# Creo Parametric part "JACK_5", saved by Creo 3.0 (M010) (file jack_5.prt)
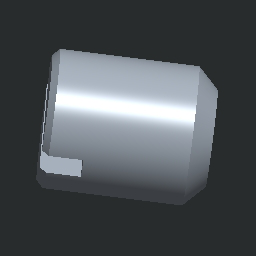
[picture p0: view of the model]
Units: millimeter Newton Second (mmNs); MM, TONNE, SECS

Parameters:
  PLACEMENT = "EXTERNAL"

Other parameters: MINOR_DIAMETER, PITCH

Created from: MMNS_PART_SOLID.PRT

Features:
  1. datum plane "RIGHT"
  2. datum plane "TOP"
  3. datum plane "FRONT"
  4. coordinate system
  5. protrusion
  6. chamfer
  7. cut
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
